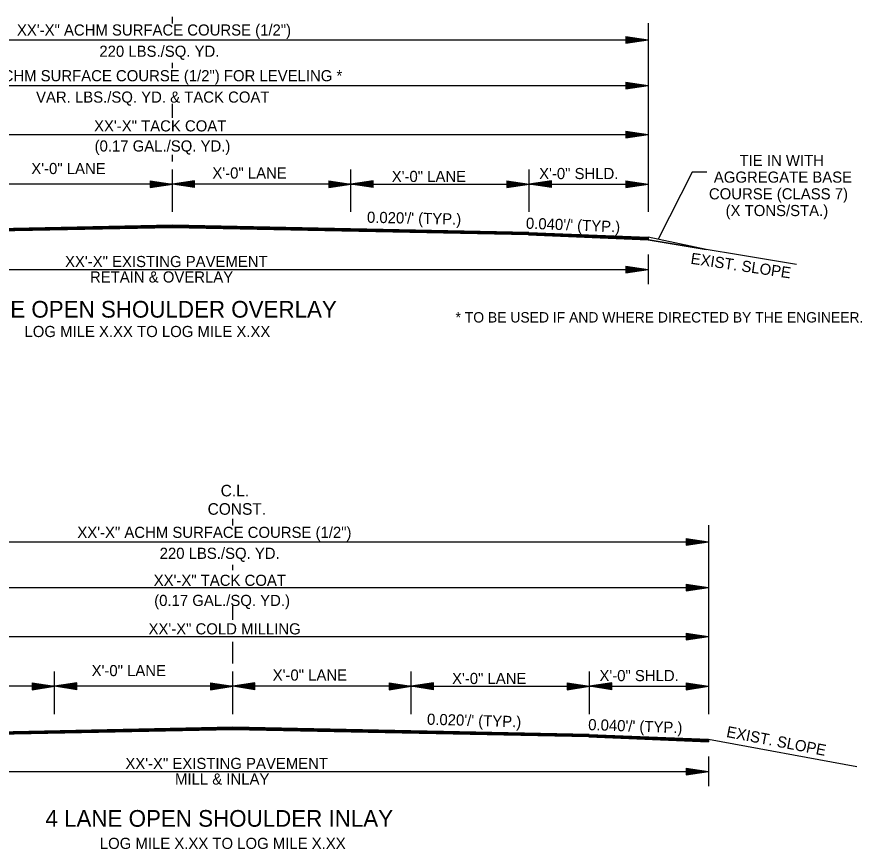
# Model space of a CAD drawing. Extents: x 544199 to 1930787, y -1968972 to 596640.
# Drawn here: x 551801 to 552370, y -1962426 to -1961865 of the extents above; entities that cross this region are included whole.
import ezdxf

# ---------------------------------------------------------------- set-up
doc = ezdxf.new("R2010")
doc.units = 0
doc.layers.add('R_Border Prem', color=7, linetype='Continuous')
doc.layers.add('R_Draft', color=7, linetype='Continuous')

msp = doc.modelspace()

# ---------------------------------------------------------------- linework, layer by layer
at = {"layer": 'R_Draft'}
for p, q in [((551905.48, -1961869.83), (551905.48, -1961865.42)), ((551585.29, -1961880.81), (552225.74, -1961880.81)), ((552210.74, -1961878.56), (552225.74, -1961880.81)), ((552210.74, -1961878.56), (552210.74, -1961883.06)), ((552210.74, -1961878.94), (552223.24, -1961880.81)), ((552210.74, -1961879.32), (552220.66, -1961880.81)), ((552210.74, -1961879.7), (552218.16, -1961880.81)), ((552210.74, -1961880.09), (552215.62, -1961880.81)), ((552210.74, -1961880.46), (552213.11, -1961880.81)), ((552210.74, -1961883.06), (552225.74, -1961880.81)), ((552210.74, -1961881.55), (552215.62, -1961880.81)), ((552210.74, -1961882.31), (552220.66, -1961880.81)), ((552210.74, -1961882.69), (552223.24, -1961880.81)), ((552210.74, -1961881.93), (552218.16, -1961880.81)), ((552210.74, -1961881.17), (552213.11, -1961880.81)), ((551905.48, -1961899.96), (551905.48, -1961896.29)), ((552210.74, -1961909.43), (552225.74, -1961911.68)), ((552210.74, -1961909.43), (552210.74, -1961913.93)), ((552210.74, -1961909.81), (552223.24, -1961911.68)), ((552210.74, -1961910.19), (552220.66, -1961911.68)), ((552210.74, -1961910.57), (552218.16, -1961911.68)), ((552210.74, -1961910.96), (552215.62, -1961911.68)), ((551585.29, -1961911.68), (552225.74, -1961911.68)), ((552210.74, -1961911.33), (552213.11, -1961911.68)), ((552210.74, -1961913.93), (552225.74, -1961911.68)), ((552210.74, -1961912.42), (552215.62, -1961911.68)), ((552210.74, -1961913.18), (552220.66, -1961911.68)), ((552210.74, -1961913.56), (552223.24, -1961911.68)), ((552210.74, -1961912.8), (552218.16, -1961911.68)), ((552210.74, -1961912.04), (552213.11, -1961911.68)), ((551905.48, -1961933.32), (551905.48, -1961924.02)), ((551585.29, -1961944.61), (552225.74, -1961944.61)), ((552210.74, -1961942.36), (552225.74, -1961944.61)), ((552210.74, -1961942.36), (552210.74, -1961946.86)), ((552210.74, -1961942.74), (552223.24, -1961944.61)), ((552210.74, -1961943.12), (552220.66, -1961944.61)), ((552210.74, -1961943.49), (552218.16, -1961944.61)), ((552210.74, -1961943.88), (552215.62, -1961944.61)), ((552210.74, -1961944.26), (552213.11, -1961944.61)), ((552210.74, -1961946.86), (552225.74, -1961944.61)), ((552210.74, -1961945.35), (552215.62, -1961944.61)), ((552210.74, -1961946.1), (552220.66, -1961944.61)), ((552210.74, -1961946.49), (552223.24, -1961944.61)), ((552210.74, -1961945.73), (552218.16, -1961944.61)), ((552210.74, -1961944.96), (552213.11, -1961944.61)), ((551905.48, -1961962.76), (551905.48, -1961958.39)), ((551905.48, -1961978.15), (551905.48, -1961968.26)), ((551905.48, -1961996.81), (551905.48, -1961968.26)), ((552025.74, -1961996.8), (552025.74, -1961968.25)), ((552145.74, -1961996.8), (552145.74, -1961968.25)), ((551905.48, -1961978.15), (551785.55, -1961978.15)), ((551890.48, -1961975.9), (551905.48, -1961978.15)), ((551890.48, -1961975.9), (551890.48, -1961980.4)), ((551890.48, -1961976.27), (551902.98, -1961978.15)), ((551890.48, -1961976.66), (551900.4, -1961978.15)), ((551890.48, -1961977.03), (551897.9, -1961978.15)), ((551890.48, -1961977.42), (551895.36, -1961978.15)), ((551890.48, -1961977.8), (551892.85, -1961978.15)), ((551890.48, -1961980.4), (551905.48, -1961978.15)), ((551890.48, -1961978.88), (551895.36, -1961978.15)), ((551890.48, -1961979.64), (551900.4, -1961978.15)), ((551890.48, -1961980.02), (551902.98, -1961978.15)), ((551890.48, -1961979.27), (551897.9, -1961978.15)), ((551890.48, -1961978.5), (551892.85, -1961978.15)), ((551920.48, -1961975.9), (551905.48, -1961978.15)), ((551905.48, -1961996.81), (551905.48, -1961978.15)), ((552025.74, -1961978.15), (551905.48, -1961978.15)), ((551920.48, -1961980.4), (551905.48, -1961978.15)), ((551920.48, -1961976.27), (551907.99, -1961978.15)), ((551920.48, -1961980.02), (551907.99, -1961978.15)), ((551920.48, -1961976.66), (551910.57, -1961978.15)), ((551920.48, -1961979.64), (551910.57, -1961978.15)), ((551920.48, -1961977.03), (551913.06, -1961978.15)), ((551920.48, -1961979.27), (551913.06, -1961978.15)), ((551920.48, -1961977.41), (551915.61, -1961978.15)), ((551920.48, -1961978.88), (551915.61, -1961978.15)), ((551920.48, -1961977.8), (551918.11, -1961978.15)), ((551920.48, -1961978.5), (551918.11, -1961978.15)), ((551920.48, -1961980.4), (551920.48, -1961975.9)), ((552010.74, -1961975.9), (552025.74, -1961978.15)), ((552010.74, -1961975.9), (552010.74, -1961980.4)), ((552010.74, -1961976.27), (552023.24, -1961978.15)), ((552010.74, -1961976.66), (552020.66, -1961978.15)), ((552010.74, -1961977.03), (552018.16, -1961978.15)), ((552010.74, -1961977.42), (552015.62, -1961978.15)), ((552010.74, -1961977.8), (552013.11, -1961978.15)), ((552010.74, -1961980.4), (552025.74, -1961978.15)), ((552010.74, -1961978.88), (552015.62, -1961978.15)), ((552010.74, -1961979.64), (552020.66, -1961978.15)), ((552010.74, -1961980.02), (552023.24, -1961978.15)), ((552010.74, -1961979.27), (552018.16, -1961978.15)), ((552010.74, -1961978.5), (552013.11, -1961978.15)), ((552040.74, -1961975.9), (552025.74, -1961978.15)), ((552025.74, -1961978.15), (552145.74, -1961978.15)), ((552040.74, -1961980.4), (552025.74, -1961978.15)), ((552040.74, -1961976.27), (552028.25, -1961978.15)), ((552040.74, -1961980.02), (552028.25, -1961978.15)), ((552040.74, -1961976.66), (552030.83, -1961978.15)), ((552040.74, -1961979.64), (552030.83, -1961978.15)), ((552040.74, -1961977.03), (552033.32, -1961978.15)), ((552040.74, -1961979.27), (552033.32, -1961978.15)), ((552040.74, -1961977.41), (552035.87, -1961978.15)), ((552040.74, -1961978.88), (552035.87, -1961978.15)), ((552040.74, -1961977.8), (552038.37, -1961978.15)), ((552040.74, -1961978.5), (552038.37, -1961978.15)), ((552040.74, -1961980.4), (552040.74, -1961975.9)), ((552130.74, -1961975.9), (552145.74, -1961978.15)), ((552130.74, -1961975.9), (552130.74, -1961980.4)), ((552130.74, -1961976.27), (552143.24, -1961978.15)), ((552130.74, -1961976.66), (552140.66, -1961978.15)), ((552130.74, -1961977.03), (552138.16, -1961978.15)), ((552130.74, -1961977.42), (552135.62, -1961978.15)), ((552130.74, -1961977.8), (552133.11, -1961978.15)), ((552130.74, -1961980.4), (552145.74, -1961978.15)), ((552130.74, -1961978.88), (552135.62, -1961978.15)), ((552130.74, -1961979.64), (552140.66, -1961978.15)), ((552130.74, -1961980.02), (552143.24, -1961978.15)), ((552130.74, -1961979.27), (552138.16, -1961978.15)), ((552130.74, -1961978.5), (552133.11, -1961978.15)), ((552160.74, -1961975.9), (552145.74, -1961978.15)), ((552145.74, -1961978.15), (552225.74, -1961978.15)), ((552160.74, -1961980.4), (552145.74, -1961978.15)), ((552160.74, -1961976.27), (552148.25, -1961978.15)), ((552160.74, -1961980.02), (552148.25, -1961978.15)), ((552160.74, -1961976.66), (552150.83, -1961978.15)), ((552160.74, -1961979.64), (552150.83, -1961978.15)), ((552160.74, -1961977.03), (552153.32, -1961978.15)), ((552160.74, -1961979.27), (552153.32, -1961978.15)), ((552160.74, -1961977.41), (552155.87, -1961978.15)), ((552160.74, -1961978.88), (552155.87, -1961978.15)), ((552160.74, -1961977.8), (552158.37, -1961978.15)), ((552160.74, -1961978.5), (552158.37, -1961978.15)), ((552160.74, -1961980.4), (552160.74, -1961975.9)), ((552210.74, -1961975.9), (552225.74, -1961978.15)), ((552210.74, -1961975.9), (552210.74, -1961980.4)), ((552210.74, -1961976.27), (552223.24, -1961978.15)), ((552210.74, -1961976.66), (552220.66, -1961978.15)), ((552210.74, -1961977.03), (552218.16, -1961978.15)), ((552210.74, -1961977.42), (552215.62, -1961978.15)), ((552210.74, -1961977.8), (552213.11, -1961978.15)), ((552210.74, -1961980.4), (552225.74, -1961978.15)), ((552210.74, -1961978.88), (552215.62, -1961978.15)), ((552210.74, -1961979.64), (552220.66, -1961978.15)), ((552210.74, -1961980.02), (552223.24, -1961978.15)), ((552210.74, -1961979.27), (552218.16, -1961978.15)), ((552210.74, -1961978.5), (552213.11, -1961978.15)), ((551905.48, -1961993.56), (551905.48, -1961980.27)), ((551905.48, -1962005.76), (551665.55, -1962010.55)), ((551905.49, -1962006.05), (551665.56, -1962010.85)), ((551905.49, -1962006.35), (551665.57, -1962011.15)), ((551905.5, -1962006.65), (551665.57, -1962011.45)), ((551905.51, -1962006.95), (551665.58, -1962011.75)), ((551905.51, -1962007.25), (551665.58, -1962012.05)), ((551905.52, -1962007.45), (551665.59, -1962012.25)), ((552145.38, -1962012.05), (551905.45, -1962007.25)), ((552145.37, -1962012.25), (551905.45, -1962007.45)), ((552145.39, -1962011.45), (551905.46, -1962006.65)), ((552145.38, -1962011.75), (551905.46, -1962006.95)), ((552145.4, -1962011.15), (551905.47, -1962006.35)), ((552145.41, -1962010.55), (551905.48, -1962005.76)), ((552145.4, -1962010.85), (551905.48, -1962006.05)), ((552145.34, -1962012.25), (552225.74, -1962015.47)), ((552145.35, -1962012.05), (552225.74, -1962015.27)), ((552145.36, -1962011.75), (552225.74, -1962014.97)), ((552145.37, -1962011.45), (552225.74, -1962014.67)), ((552145.38, -1962011.15), (552225.74, -1962014.37)), ((552145.4, -1962010.85), (552225.74, -1962014.07)), ((552145.41, -1962010.55), (552225.74, -1962013.77)), ((552225.74, -1962013.77), (552225.74, -1962015.47)), ((552264.99, -1962022), (552225.74, -1962013.77)), ((552225.74, -1962013.77), (552225.74, -1962015.47)), ((552225.74, -1962013.77), (552225.74, -1962015.47)), ((552225.74, -1962013.77), (552225.74, -1962015.47)), ((552325.81, -1962032.14), (552225.74, -1962015.47)), ((552225.74, -1962015.47), (552225.74, -1962015.47)), ((552225.74, -1962015.47), (552264.99, -1962022)), ((552225.74, -1962025.36), (552225.74, -1962045.36)), ((551585.29, -1962035.61), (552225.74, -1962035.61)), ((552210.74, -1962033.36), (552225.74, -1962035.61)), ((552210.74, -1962033.36), (552210.74, -1962037.86)), ((552210.74, -1962033.74), (552223.24, -1962035.61)), ((552210.74, -1962034.12), (552220.66, -1962035.61)), ((552210.74, -1962034.5), (552218.16, -1962035.61)), ((552210.74, -1962034.89), (552215.62, -1962035.61)), ((552210.74, -1962035.26), (552213.11, -1962035.61)), ((552210.74, -1962037.86), (552225.74, -1962035.61)), ((552210.74, -1962036.35), (552215.62, -1962035.61)), ((552210.74, -1962037.11), (552220.66, -1962035.61)), ((552210.74, -1962037.49), (552223.24, -1962035.61)), ((552210.74, -1962036.73), (552218.16, -1962035.61)), ((552210.74, -1962035.97), (552213.11, -1962035.61)), ((551946.1, -1962208), (551946.1, -1962203.59)), ((552251.36, -1962216.73), (552266.36, -1962218.98)), ((552251.36, -1962216.73), (552251.36, -1962221.23)), ((552251.36, -1962217.11), (552263.85, -1962218.98)), ((552251.36, -1962217.49), (552261.27, -1962218.98)), ((552251.36, -1962217.87), (552258.78, -1962218.98)), ((552251.36, -1962218.26), (552256.23, -1962218.98)), ((551625.91, -1962218.98), (552266.36, -1962218.98)), ((552251.36, -1962218.63), (552253.73, -1962218.98)), ((552251.36, -1962221.23), (552266.36, -1962218.98)), ((552251.36, -1962219.72), (552256.23, -1962218.98)), ((552251.36, -1962220.48), (552261.27, -1962218.98)), ((552251.36, -1962220.86), (552263.85, -1962218.98)), ((552251.36, -1962220.1), (552258.78, -1962218.98)), ((552251.36, -1962219.34), (552253.73, -1962218.98)), ((551946.1, -1962238.13), (551946.1, -1962234.46)), ((551625.91, -1962249.85), (552266.36, -1962249.85)), ((552251.36, -1962247.6), (552266.36, -1962249.85)), ((552251.36, -1962247.6), (552251.36, -1962252.1)), ((552251.36, -1962247.98), (552263.85, -1962249.85)), ((552251.36, -1962248.36), (552261.27, -1962249.85)), ((552251.36, -1962248.74), (552258.78, -1962249.85)), ((552251.36, -1962249.13), (552256.23, -1962249.85)), ((552251.36, -1962249.5), (552253.73, -1962249.85)), ((552251.36, -1962252.1), (552266.36, -1962249.85)), ((552251.36, -1962250.59), (552256.23, -1962249.85)), ((552251.36, -1962251.35), (552261.27, -1962249.85)), ((552251.36, -1962251.73), (552263.85, -1962249.85)), ((552251.36, -1962250.97), (552258.78, -1962249.85)), ((552251.36, -1962250.21), (552253.73, -1962249.85)), ((551946.1, -1962271.49), (551946.1, -1962262.19)), ((552251.36, -1962280.53), (552266.36, -1962282.78)), ((552251.36, -1962280.53), (552251.36, -1962285.03)), ((552251.36, -1962280.91), (552263.85, -1962282.78)), ((551625.91, -1962282.78), (552266.36, -1962282.78)), ((551946.1, -1962300.93), (551946.1, -1962286.34)), ((552251.36, -1962281.29), (552261.27, -1962282.78)), ((552251.36, -1962281.67), (552258.78, -1962282.78)), ((552251.36, -1962282.06), (552256.23, -1962282.78)), ((552251.36, -1962282.43), (552253.73, -1962282.78)), ((552251.36, -1962285.03), (552266.36, -1962282.78)), ((552251.36, -1962283.52), (552256.23, -1962282.78)), ((552251.36, -1962284.28), (552261.27, -1962282.78)), ((552251.36, -1962284.66), (552263.85, -1962282.78)), ((552251.36, -1962283.9), (552258.78, -1962282.78)), ((552251.36, -1962283.14), (552253.73, -1962282.78)), ((551826.17, -1962334.98), (551826.17, -1962306.43)), ((551946.1, -1962316.32), (551946.1, -1962306.43)), ((551946.1, -1962334.98), (551946.1, -1962306.43)), ((552066.36, -1962334.97), (552066.36, -1962306.42)), ((552186.36, -1962334.97), (552186.36, -1962306.42)), ((551811.17, -1962314.07), (551826.17, -1962316.32)), ((551811.17, -1962314.07), (551811.17, -1962318.57)), ((551811.17, -1962314.44), (551823.67, -1962316.32)), ((551811.17, -1962314.83), (551821.09, -1962316.32)), ((551841.17, -1962314.07), (551826.17, -1962316.32)), ((551841.17, -1962314.44), (551828.68, -1962316.32)), ((551841.17, -1962314.83), (551831.26, -1962316.32)), ((551841.17, -1962318.57), (551841.17, -1962314.07)), ((551931.1, -1962314.07), (551946.1, -1962316.32)), ((551931.1, -1962314.07), (551931.1, -1962318.57)), ((551931.1, -1962314.44), (551943.59, -1962316.32)), ((551931.1, -1962314.83), (551941.01, -1962316.32)), ((551961.1, -1962314.07), (551946.1, -1962316.32)), ((551961.1, -1962314.44), (551948.6, -1962316.32)), ((551961.1, -1962314.83), (551951.18, -1962316.32)), ((551961.1, -1962318.57), (551961.1, -1962314.07)), ((552051.36, -1962314.07), (552066.36, -1962316.32)), ((552051.36, -1962314.07), (552051.36, -1962318.57)), ((552051.36, -1962314.44), (552063.85, -1962316.32)), ((552051.36, -1962314.83), (552061.27, -1962316.32)), ((552081.36, -1962314.07), (552066.36, -1962316.32)), ((552081.36, -1962314.44), (552068.86, -1962316.32)), ((552081.36, -1962314.83), (552071.44, -1962316.32)), ((552081.36, -1962318.57), (552081.36, -1962314.07)), ((552171.36, -1962314.07), (552186.36, -1962316.32)), ((552171.36, -1962314.07), (552171.36, -1962318.57)), ((552171.36, -1962314.44), (552183.85, -1962316.32)), ((552171.36, -1962314.83), (552181.27, -1962316.32)), ((552201.36, -1962314.07), (552186.36, -1962316.32)), ((552201.36, -1962314.44), (552188.86, -1962316.32)), ((552201.36, -1962314.83), (552191.44, -1962316.32)), ((552201.36, -1962318.57), (552201.36, -1962314.07)), ((552251.36, -1962314.07), (552266.36, -1962316.32)), ((552251.36, -1962314.07), (552251.36, -1962318.57)), ((552251.36, -1962314.44), (552263.85, -1962316.32)), ((552251.36, -1962314.83), (552261.27, -1962316.32)), ((551826.17, -1962316.32), (551706.17, -1962316.32)), ((551811.17, -1962315.2), (551818.59, -1962316.32)), ((551811.17, -1962315.59), (551816.05, -1962316.32)), ((551811.17, -1962315.97), (551813.54, -1962316.32)), ((551811.17, -1962318.57), (551826.17, -1962316.32)), ((551811.17, -1962317.05), (551816.05, -1962316.32)), ((551811.17, -1962317.81), (551821.09, -1962316.32)), ((551811.17, -1962318.19), (551823.67, -1962316.32)), ((551811.17, -1962317.44), (551818.59, -1962316.32)), ((551811.17, -1962316.67), (551813.54, -1962316.32)), ((551946.1, -1962316.32), (551826.17, -1962316.32)), ((551841.17, -1962318.57), (551826.17, -1962316.32)), ((551841.17, -1962318.19), (551828.68, -1962316.32)), ((551841.17, -1962317.81), (551831.26, -1962316.32)), ((551841.17, -1962315.2), (551833.75, -1962316.32)), ((551841.17, -1962317.44), (551833.75, -1962316.32)), ((551841.17, -1962315.58), (551836.3, -1962316.32)), ((551841.17, -1962317.05), (551836.3, -1962316.32)), ((551841.17, -1962315.97), (551838.8, -1962316.32)), ((551841.17, -1962316.67), (551838.8, -1962316.32)), ((551931.1, -1962315.2), (551938.52, -1962316.32)), ((551931.1, -1962315.59), (551935.97, -1962316.32)), ((551931.1, -1962315.97), (551933.47, -1962316.32)), ((551931.1, -1962318.57), (551946.1, -1962316.32)), ((551931.1, -1962317.05), (551935.97, -1962316.32)), ((551931.1, -1962317.81), (551941.01, -1962316.32)), ((551931.1, -1962318.19), (551943.59, -1962316.32)), ((551931.1, -1962317.44), (551938.52, -1962316.32)), ((551931.1, -1962316.67), (551933.47, -1962316.32)), ((551946.1, -1962334.98), (551946.1, -1962316.32)), ((552066.36, -1962316.32), (551946.1, -1962316.32)), ((551961.1, -1962318.57), (551946.1, -1962316.32)), ((551946.1, -1962331.73), (551946.1, -1962318.44)), ((551961.1, -1962318.19), (551948.6, -1962316.32)), ((551961.1, -1962317.81), (551951.18, -1962316.32)), ((551961.1, -1962315.2), (551953.68, -1962316.32)), ((551961.1, -1962317.44), (551953.68, -1962316.32)), ((551961.1, -1962315.58), (551956.22, -1962316.32)), ((551961.1, -1962317.05), (551956.22, -1962316.32)), ((551961.1, -1962315.97), (551958.73, -1962316.32)), ((551961.1, -1962316.67), (551958.73, -1962316.32)), ((552051.36, -1962315.2), (552058.78, -1962316.32)), ((552051.36, -1962315.59), (552056.23, -1962316.32)), ((552051.36, -1962315.97), (552053.73, -1962316.32)), ((552051.36, -1962318.57), (552066.36, -1962316.32)), ((552051.36, -1962317.05), (552056.23, -1962316.32)), ((552051.36, -1962317.81), (552061.27, -1962316.32)), ((552051.36, -1962318.19), (552063.85, -1962316.32)), ((552051.36, -1962317.44), (552058.78, -1962316.32)), ((552051.36, -1962316.67), (552053.73, -1962316.32)), ((552066.36, -1962316.32), (552186.36, -1962316.32)), ((552081.36, -1962318.57), (552066.36, -1962316.32)), ((552081.36, -1962318.19), (552068.86, -1962316.32)), ((552081.36, -1962317.81), (552071.44, -1962316.32)), ((552081.36, -1962315.2), (552073.94, -1962316.32)), ((552081.36, -1962317.44), (552073.94, -1962316.32)), ((552081.36, -1962315.58), (552076.48, -1962316.32)), ((552081.36, -1962317.05), (552076.48, -1962316.32)), ((552081.36, -1962315.97), (552078.99, -1962316.32)), ((552081.36, -1962316.67), (552078.99, -1962316.32)), ((552171.36, -1962315.2), (552178.78, -1962316.32)), ((552171.36, -1962315.59), (552176.23, -1962316.32)), ((552171.36, -1962315.97), (552173.73, -1962316.32)), ((552171.36, -1962318.57), (552186.36, -1962316.32)), ((552171.36, -1962317.05), (552176.23, -1962316.32)), ((552171.36, -1962317.81), (552181.27, -1962316.32)), ((552171.36, -1962318.19), (552183.85, -1962316.32)), ((552171.36, -1962317.44), (552178.78, -1962316.32)), ((552171.36, -1962316.67), (552173.73, -1962316.32)), ((552186.36, -1962316.32), (552266.36, -1962316.32)), ((552201.36, -1962318.57), (552186.36, -1962316.32)), ((552201.36, -1962318.19), (552188.86, -1962316.32)), ((552201.36, -1962317.81), (552191.44, -1962316.32)), ((552201.36, -1962315.2), (552193.94, -1962316.32)), ((552201.36, -1962317.44), (552193.94, -1962316.32)), ((552201.36, -1962315.58), (552196.48, -1962316.32)), ((552201.36, -1962317.05), (552196.48, -1962316.32)), ((552201.36, -1962315.97), (552198.99, -1962316.32)), ((552201.36, -1962316.67), (552198.99, -1962316.32)), ((552251.36, -1962315.2), (552258.78, -1962316.32)), ((552251.36, -1962315.59), (552256.23, -1962316.32)), ((552251.36, -1962315.97), (552253.73, -1962316.32)), ((552251.36, -1962318.57), (552266.36, -1962316.32)), ((552251.36, -1962317.05), (552256.23, -1962316.32)), ((552251.36, -1962317.81), (552261.27, -1962316.32)), ((552251.36, -1962318.19), (552263.85, -1962316.32)), ((552251.36, -1962317.44), (552258.78, -1962316.32)), ((552251.36, -1962316.67), (552253.73, -1962316.32)), ((551946.1, -1962343.93), (551706.17, -1962348.72)), ((551946.1, -1962344.23), (551706.18, -1962349.02)), ((551946.11, -1962344.53), (551706.18, -1962349.32)), ((551946.12, -1962344.83), (551706.19, -1962349.62)), ((551946.12, -1962345.13), (551706.2, -1962349.92)), ((551946.13, -1962345.43), (551706.2, -1962350.22)), ((551946.13, -1962345.63), (551706.21, -1962350.42)), ((552185.99, -1962350.42), (551946.06, -1962345.63)), ((552186, -1962349.92), (551946.07, -1962345.13)), ((552186, -1962350.22), (551946.07, -1962345.43)), ((552186.01, -1962349.62), (551946.08, -1962344.83)), ((552186.02, -1962349.02), (551946.09, -1962344.23)), ((552186.01, -1962349.32), (551946.09, -1962344.53)), ((552186.03, -1962348.72), (551946.1, -1962343.93)), ((552186, -1962349.32), (552266.36, -1962352.54)), ((552186.01, -1962349.02), (552266.36, -1962352.24)), ((552186.03, -1962348.72), (552266.36, -1962351.94)), ((552185.96, -1962350.42), (552266.36, -1962353.64)), ((552185.97, -1962350.22), (552266.36, -1962353.44)), ((552185.98, -1962349.92), (552266.36, -1962353.14)), ((552185.99, -1962349.62), (552266.36, -1962352.84)), ((552266.36, -1962351.94), (552266.36, -1962353.64)), ((552266.36, -1962351.94), (552266.36, -1962353.64)), ((552266.36, -1962351.94), (552366.43, -1962370.32)), ((552266.36, -1962363.54), (552266.36, -1962383.54)), ((552251.36, -1962371.53), (552266.36, -1962373.78)), ((552251.36, -1962371.53), (552251.36, -1962376.03)), ((552251.36, -1962371.91), (552263.85, -1962373.78)), ((551625.91, -1962373.78), (552266.36, -1962373.78)), ((552251.36, -1962372.29), (552261.27, -1962373.78)), ((552251.36, -1962372.67), (552258.78, -1962373.78)), ((552251.36, -1962373.06), (552256.23, -1962373.78)), ((552251.36, -1962373.43), (552253.73, -1962373.78)), ((552251.36, -1962376.03), (552266.36, -1962373.78)), ((552251.36, -1962374.52), (552256.23, -1962373.78)), ((552251.36, -1962375.28), (552261.27, -1962373.78)), ((552251.36, -1962375.66), (552263.85, -1962373.78)), ((552251.36, -1962374.9), (552258.78, -1962373.78)), ((552251.36, -1962374.14), (552253.73, -1962373.78))]:
    msp.add_line(p, q, dxfattribs=at)
for points in [[(552225.74, -1961869.55), (552225.74, -1961996.8)], [(552265.43, -1961969.93), (552255.43, -1961969.93), (552232.65, -1962015.22)], [(552266.36, -1962207.72), (552266.36, -1962334.97)]]:
    msp.add_lwpolyline(points, dxfattribs=at)

# ---------------------------------------------------------------- texts
at = {"layer": 'R_Border Prem'}
msp.add_text('* TO BE USED IF AND WHERE DIRECTED BY THE ENGINEER.', height=7, dxfattribs=at).set_placement((552096.13, -1962071.28))
at = {"layer": 'R_Draft'}
for s, height, p in [('XX\'-X" ACHM SURFACE COURSE (1/2")', 7.5, (551800.83, -1961877.99)), ('220 LBS./SQ. YD. ', 7.5, (551856.31, -1961892.31)), ('XX\'-X" ACHM SURFACE COURSE (1/2") FOR LEVELING *', 7.5, (551752.81, -1961908.78)), ('VAR. LBS./SQ. YD. & TACK COAT', 7.5, (551813.7, -1961923.18)), ('XX\'-X" TACK COAT', 7.5, (551852.76, -1961942.57)), ('(0.17 GAL./SQ. YD.)', 7.5, (551853.12, -1961956.11)), ('TIE IN WITH ', 7.5, (552287.37, -1961965.83)), ('X\'-0" LANE', 7.5, (551810.49, -1961971.29)), ('X\'-0" LANE', 7.5, (551932.44, -1961974.31)), ('X\'-0" SHLD.', 7.5, (552152.43, -1961974.66)), ('X\'-0" LANE', 7.5, (552053.19, -1961976.61)), ('AGGREGATE BASE', 7.5, (552270.07, -1961977.08)), ('COURSE (CLASS 7)', 7.5, (552266.76, -1961988.33)), ('(X TONS/STA.)', 7.5, (552277.98, -1961999.58)), ('XX\'-X" EXISTING PAVEMENT', 7.5, (551833.21, -1962033.92)), ('RETAIN & OVERLAY', 7.5, (551850, -1962044.33)), ('4 LANE OPEN SHOULDER OVERLAY', 11.25, (551754.53, -1962067.98)), ('LOG MILE X.XX TO LOG MILE X.XX', 7.5, (551805.91, -1962081.07)), ('C.L.', 7.8, (551938, -1962188.39)), ('CONST.', 7.8, (551929.21, -1962200.76)), ('XX\'-X" ACHM SURFACE COURSE (1/2")', 7.5, (551841.49, -1962216.35)), ('220 LBS./SQ. YD. ', 7.5, (551896.92, -1962230.48)), ('XX\'-X" TACK COAT', 7.5, (551892.9, -1962248.67)), ('(0.17 GAL./SQ. YD.)', 7.5, (551893.25, -1962262.21)), ('XX\'-X" COLD MILLING', 7.5, (551889.42, -1962281.36)), ('X\'-0" LANE', 7.5, (551851.11, -1962309.46)), ('X\'-0" LANE', 7.5, (551973.05, -1962312.48)), ('X\'-0" LANE', 7.5, (552093.81, -1962314.78)), ('X\'-0" SHLD.', 7.5, (552193.05, -1962312.83)), ('XX\'-X" EXISTING PAVEMENT', 7.5, (551873.83, -1962372.01)), ('MILL & INLAY', 7.5, (551907.27, -1962382.51)), ('4 LANE OPEN SHOULDER INLAY', 11.25, (551820, -1962410.9)), ('LOG MILE X.XX TO LOG MILE X.XX', 7.5, (551856.63, -1962425.85))]:
    msp.add_text(s, height=height, dxfattribs=at).set_placement(p)
for s, rotation, p in [("0.020'/' (TYP.)", 358.7889, (552036.44, -1962004.05)), ("0.040'/' (TYP.)", 357.7013, (552143.42, -1962008.05)), ('EXIST. SLOPE', 351.5755, (552254.11, -1962031.65)), ("0.020'/' (TYP.)", 358.3625, (552076.85, -1962342.15)), ("0.040'/' (TYP.)", 358.0466, (552185.36, -1962345.78)), ('EXIST. SLOPE', 349.1171, (552278.09, -1962350.38))]:
    msp.add_text(s, height=7.5, rotation=rotation, dxfattribs=at).set_placement(p)

doc.saveas('drawing.dxf')
